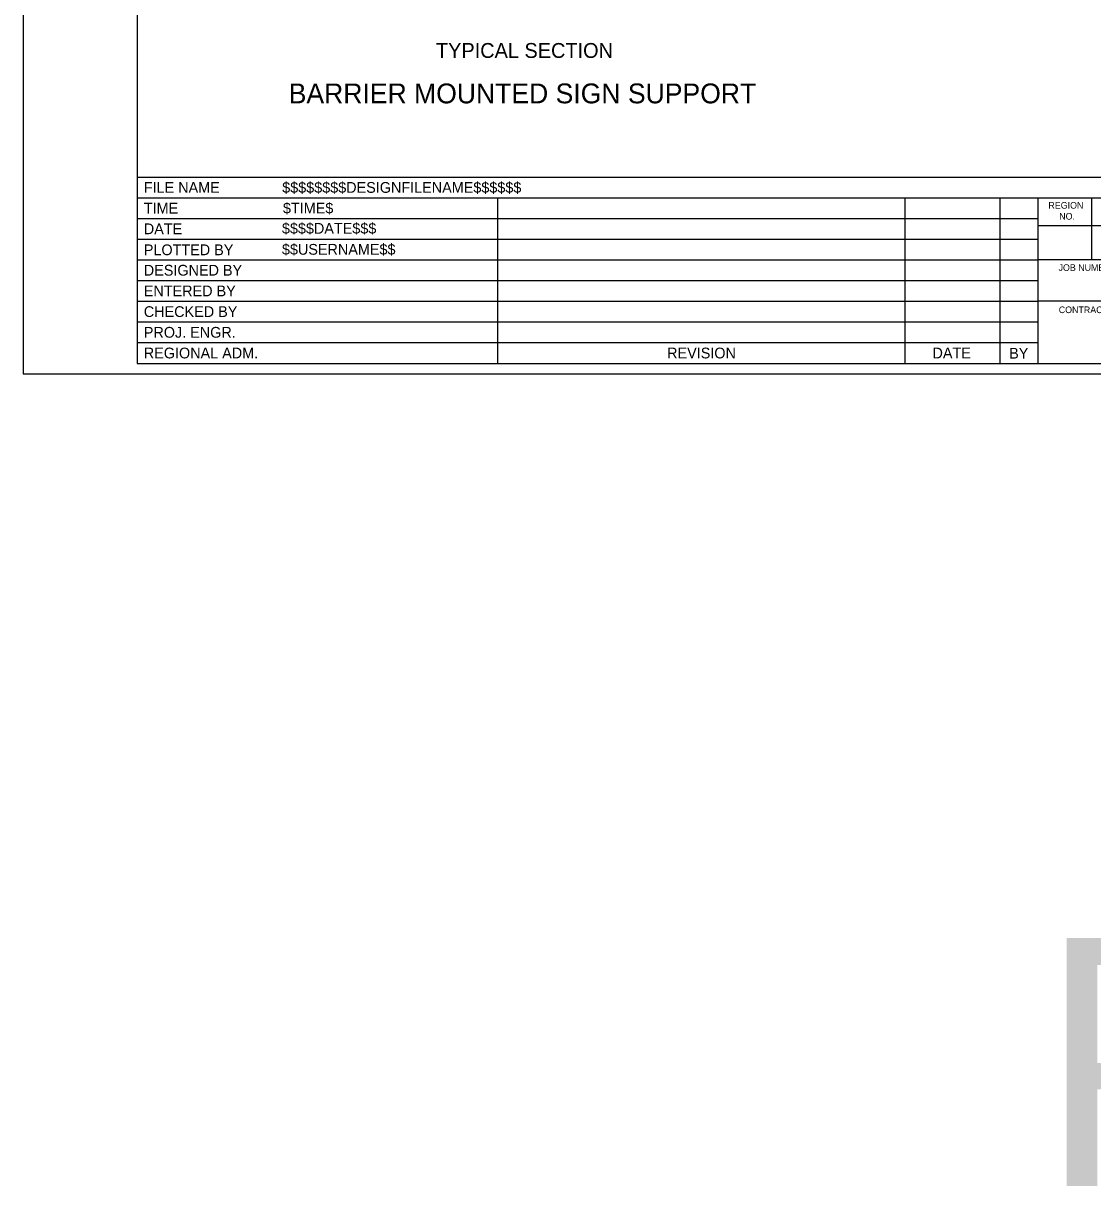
# Model space of a CAD drawing. Extents: x 99988 to 100172, y 99995 to 100047.
# Drawn here: x 99999.31 to 100005.78, y 99995.01 to 100002.06 of the extents above; entities that cross this region are included whole.
import ezdxf

# ---------------------------------------------------------------- set-up
doc = ezdxf.new("R2010")
doc.units = 0
for name, color, linetype in [('Level 20', 7, 'Continuous'), ('SH_GI_PlotLimits', 7, 'Continuous'), ('SH_GI_SheetBorder', 7, 'Continuous'), ('SH_GI_SheetLocationText', 7, 'Continuous'), ('SH_GI_SheetTextInCells', 7, 'Continuous'), ('SH_GI_TitleBlockText', 7, 'Continuous')]:
    doc.layers.add(name, color=color, linetype=linetype)

msp = doc.modelspace()

# ---------------------------------------------------------------- linework, layer by layer
at = {"layer": 'SH_GI_PlotLimits'}
msp.add_lwpolyline([(99999.3125, 99999.9375), (100015.8125, 99999.9375), (100015.8125, 100010.4375), (99999.3125, 100010.4375)], close=True, dxfattribs=at)
at = {"layer": 'SH_GI_SheetBorder'}
for p, q in [((100000, 100010.375), (100000, 100000)), ((100000, 100001.1259), (100015.75, 100001.1259)), ((100000, 100001.0008), (100007.4566, 100001.0008)), ((100002.179, 100001.0008), (100002.179, 100000)), ((100004.641, 100001.0008), (100004.641, 100000)), ((100005.2164, 100001.0008), (100005.2164, 100000)), ((100005.4451, 100001.0008), (100005.4451, 100000)), ((100005.7719, 100000.6255), (100005.7719, 100001.0008)), ((100000, 100000.8757), (100002.1821, 100000.8757)), ((100002.1821, 100000.8757), (100005.4466, 100000.8757)), ((100006.0958, 100000.831), (100005.4466, 100000.831)), ((100000, 100000.7506), (100002.1821, 100000.7506)), ((100002.1821, 100000.7506), (100005.4466, 100000.7506)), ((100000, 100000.6255), (100005.4466, 100000.6255)), ((100006.0958, 100000.6255), (100005.4466, 100000.6255)), ((100000, 100000.5004), (100005.4466, 100000.5004)), ((100000, 100000.3753), (100005.4466, 100000.3753)), ((100007.4566, 100000.3753), (100005.4466, 100000.3753)), ((100000, 100000.2502), (100005.4466, 100000.2502)), ((100000, 100000.1251), (100005.4466, 100000.1251)), ((100000, 100000), (100015.75, 100000))]:
    msp.add_line(p, q, dxfattribs=at)

# ---------------------------------------------------------------- texts
at = {"layer": 'Level 20'}
for s, height, p in [('TYPICAL SECTION', 0.09, (100001.8072, 100001.8462)), ('BARRIER MOUNTED SIGN SUPPORT', 0.12, (100000.917, 100001.5716))]:
    msp.add_text(s, height=height, dxfattribs=at).set_placement(p)
at = {"layer": 'SH_GI_SheetLocationText'}
msp.add_text('Plot 1', height=1.5, dxfattribs=at).set_placement((100005.4547, 99995.0267))
at = {"layer": 'SH_GI_SheetTextInCells'}
for s, height, p in [('FILE NAME', 0.06505, (100000.041, 100001.0308)), ('TIME', 0.06505, (100000.041, 100000.9057)), ('REGION', 0.04003, (100005.5099, 100000.9352)), ('DATE', 0.06505, (100000.041, 100000.7806)), ('NO.', 0.04003, (100005.5752, 100000.869)), ('PLOTTED BY', 0.06505, (100000.041, 100000.6538)), ('DESIGNED BY', 0.065052, (100000.041, 100000.5304)), ('JOB NUMBER', 0.04003, (100005.5712, 100000.5587)), ('ENTERED BY', 0.06505, (100000.041, 100000.4053)), ('CHECKED BY', 0.06505, (100000.041, 100000.2802)), ('CONTRACT NO.', 0.040032, (100005.5725, 100000.3037)), ('PROJ. ENGR.', 0.065052, (100000.041, 100000.1551)), ('REGIONAL ADM.', 0.065052, (100000.041, 100000.03)), ('REVISION', 0.06505, (100003.2048, 100000.03)), ('DATE', 0.06505, (100004.8091, 100000.03)), ('BY', 0.06505, (100005.2725, 100000.0285))]:
    msp.add_text(s, height=height, dxfattribs=at).set_placement(p)
at = {"layer": 'SH_GI_TitleBlockText'}
for s, height, p in [('$$$$$$$$DESIGNFILENAME$$$$$$', 0.065052, (100000.8775, 100001.0308)), ('$TIME$', 0.06505, (100000.882, 100000.9059)), ('$$$$DATE$$$', 0.065052, (100000.8759, 100000.7835)), ('$$USERNAME$$', 0.065052, (100000.8759, 100000.6567))]:
    msp.add_text(s, height=height, dxfattribs=at).set_placement(p)

doc.saveas('drawing.dxf')
